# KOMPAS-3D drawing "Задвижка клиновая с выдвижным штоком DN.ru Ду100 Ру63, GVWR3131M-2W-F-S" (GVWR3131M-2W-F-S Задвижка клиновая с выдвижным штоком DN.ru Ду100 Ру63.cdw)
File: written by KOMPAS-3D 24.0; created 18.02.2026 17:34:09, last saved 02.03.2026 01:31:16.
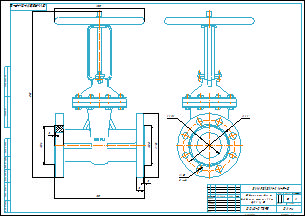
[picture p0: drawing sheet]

Document properties: art: D040-07395; Автор: R2D2; Форматы листов документа: A2; Полное имя файла: GVWR3131M-2W-F-S Задвижка клиновая с выдвижным штоком DN.ru Ду100 Ру63.m3d; Масса: 67; Наименование: Задвижка клиновая с выдвижным штоком DN.ru Ду100 Ру63; Количество листов документа: 1; Примечание: D040-07395

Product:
- Part/product: Задвижка клиновая с выдвижным штоком DN.ru Ду100 Ру63  | designation GVWR3131M-2W-F-S
    Масса: 67
    Раздел спецификации: Прочие изделия
    Форматы листов документа: A2
    Примечание: D040-07395
    additional columns: D040-07395

Referenced files in E:\Работа\Зайцев\Для компаса\: чертеж DN.ru А3.cdt
Referenced files in E:\Работа\Зайцев\GVWR3131M-2W-F-S Задвижка клиновая с выдвижным штоком DN.ru Ду50-200 Ру63\DN100\: GVWR3131M-2W-F-S Задвижка клиновая с выдвижным штоком DN.ru Ду100 Ру63.m3d
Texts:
  чертеж DN.ru А3.cdt
  Задвижка клиновая с
  выдвижным штоком DN.ru
  Ду100 Ру63
  GVWR3131M-2W-F-S
  Задвижка клиновая с выдвижным штоком DN.ru Ду100 Ру63
  GVWR3131M-2W-F-S Задвижка клиновая с выдвижным штоком DN.ru Ду100 Ру63
Dimensions and other numbers on the sheet: 1:2; 0; 1; 2; 67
